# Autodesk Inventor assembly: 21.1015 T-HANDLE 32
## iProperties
Created: 2007-03
Part Number: 21.1015 T-HANDLE 32
Document SubType Name: Assembly
Designer: Andy Moles
Translation Standard: STEP AP214IS
File Name: 1000-U417_ASM
Preprocessor: PRO/ENGINEER BY PARAMETRIC TECHNOLOGY CORPORATION, 2003200
Postprocessor: Build: 344b, Release: 11 SP2 - Date: Fri 08/18/2006
Sent Units: MILLIMETERS
Uncertainty: 0.01136958734563
Author: Andy Moles
